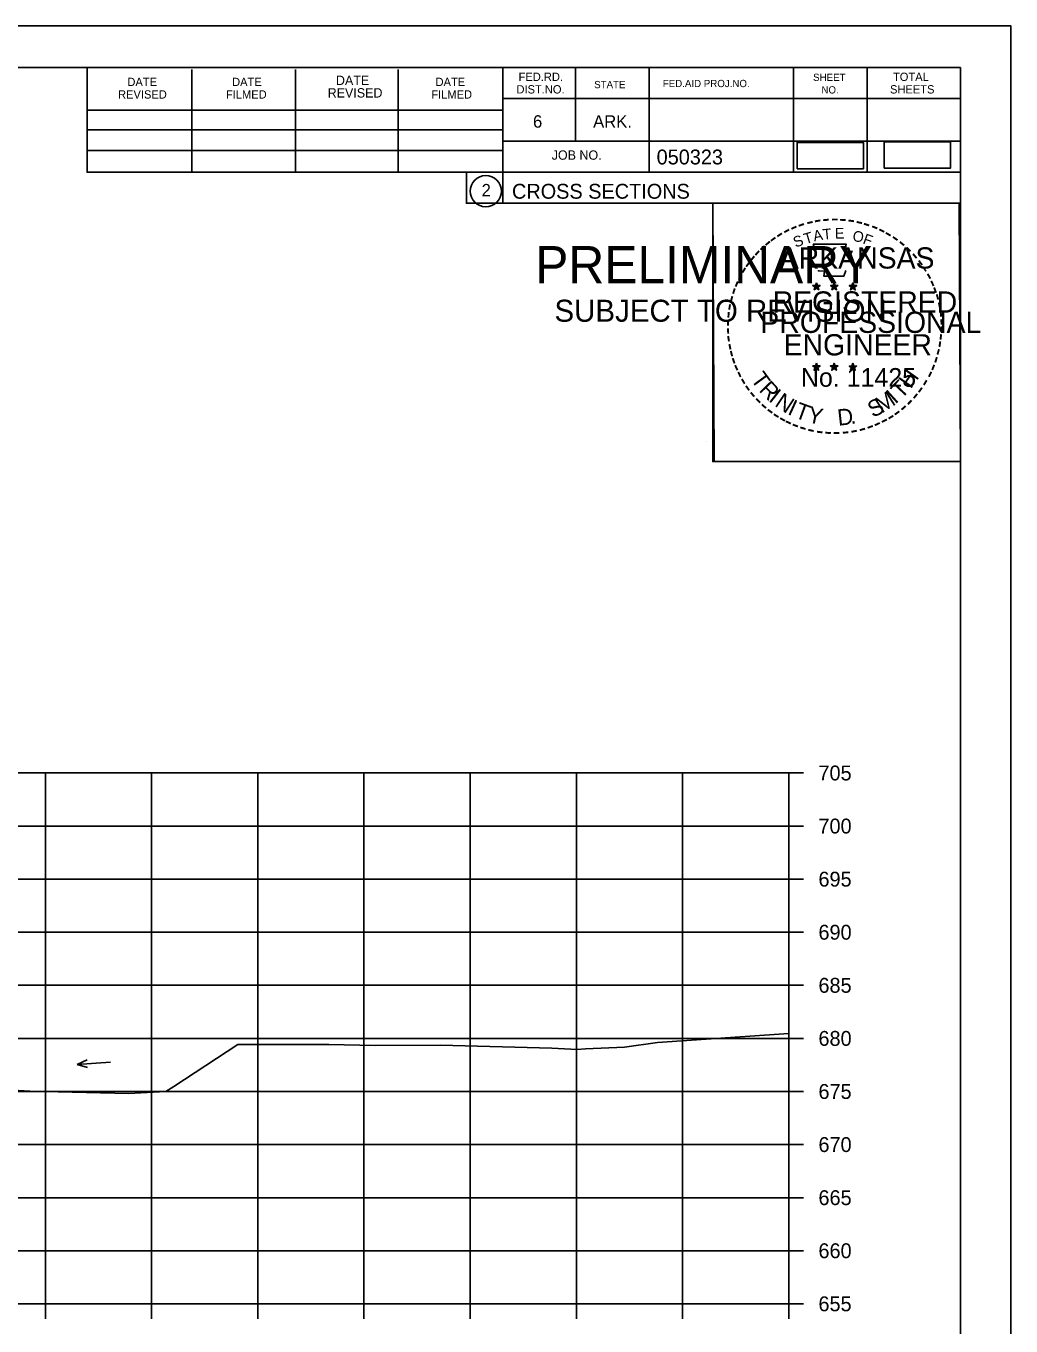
# Model space of a CAD drawing. Extents: x 1360146 to 1361431, y 631444 to 632352.
# Drawn here: x 1360386.9 to 1360479.7, y 631748.4 to 631870.8 of the extents above; entities that cross this region are included whole.
import ezdxf

# ---------------------------------------------------------------- set-up
doc = ezdxf.new("R2010")
doc.units = 0
for name, color, linetype in [('Default', 7, 'Continuous'), ('R_Axis', 7, 'Continuous'), ('R_Axis Annot', 7, 'Continuous'), ('R_Border', 7, 'Continuous'), ('R_Border PE', 7, 'Continuous'), ('R_Border Prem', 7, 'Continuous'), ('R_Exist Surface', 7, 'Continuous'), ('R_Grid', 7, 'Continuous'), ('R_No Plot', 7, 'Continuous'), ('R_Water Annot', 7, 'Continuous')]:
    doc.layers.add(name, color=color, linetype=linetype)

msp = doc.modelspace()

# ---------------------------------------------------------------- linework, layer by layer
at = {"layer": 'Default'}
for points in [[(1360459.55, 631857.39), (1360465.8, 631857.39), (1360465.8, 631859.87), (1360459.55, 631859.87)], [(1360467.76, 631857.46), (1360474.01, 631857.46), (1360474.01, 631859.93), (1360467.76, 631859.93)]]:
    msp.add_lwpolyline(points, close=True, dxfattribs=at)
at = {"layer": 'R_Axis'}
for p, q in [((1360458.77, 631750.48), (1360458.77, 631800.48)), ((1360460.17, 631800.48), (1360458.77, 631800.48)), ((1360460.17, 631795.48), (1360458.77, 631795.48)), ((1360460.17, 631790.48), (1360458.77, 631790.48)), ((1360460.17, 631785.48), (1360458.77, 631785.48)), ((1360460.17, 631780.48), (1360458.77, 631780.48)), ((1360460.17, 631775.48), (1360458.77, 631775.48)), ((1360460.17, 631770.48), (1360458.77, 631770.48)), ((1360460.17, 631765.48), (1360458.77, 631765.48)), ((1360460.17, 631760.48), (1360458.77, 631760.48)), ((1360460.17, 631755.48), (1360458.77, 631755.48)), ((1360178.77, 631750.48), (1360458.77, 631750.48)), ((1360388.77, 631749.08), (1360388.77, 631750.48)), ((1360398.77, 631749.08), (1360398.77, 631750.48)), ((1360408.77, 631749.08), (1360408.77, 631750.48)), ((1360418.77, 631749.08), (1360418.77, 631750.48)), ((1360428.77, 631749.08), (1360428.77, 631750.48)), ((1360438.77, 631749.08), (1360438.77, 631750.48)), ((1360448.77, 631749.08), (1360448.77, 631750.48)), ((1360458.77, 631749.08), (1360458.77, 631750.48)), ((1360460.17, 631750.48), (1360458.77, 631750.48))]:
    msp.add_line(p, q, dxfattribs=at)
at = {"layer": 'R_Border'}
for p, q in [((1360158.77, 631866.94), (1360474.95, 631866.94)), ((1360392.69, 631857.06), (1360392.69, 631866.94)), ((1360402.55, 631857.06), (1360402.55, 631866.74)), ((1360412.31, 631857.06), (1360412.31, 631866.74)), ((1360421.99, 631857.06), (1360421.99, 631866.74)), ((1360431.85, 631866.94), (1360431.85, 631854.14)), ((1360438.69, 631866.94), (1360438.69, 631860)), ((1360445.63, 631866.94), (1360445.63, 631857.06)), ((1360459.21, 631866.94), (1360459.21, 631857.06)), ((1360466.15, 631866.94), (1360466.15, 631857.06)), ((1360474.95, 631661.48), (1360474.95, 631866.94)), ((1360474.95, 631864), (1360431.85, 631864)), ((1360474.95, 631864.02), (1360474.95, 631864.02)), ((1360392.69, 631862.92), (1360431.85, 631862.92)), ((1360392.69, 631861.06), (1360431.85, 631861.06)), ((1360474.95, 631860), (1360431.85, 631860)), ((1360434.81, 631860), (1360474.95, 631860)), ((1360392.69, 631857.06), (1360392.69, 631859.12)), ((1360392.69, 631859.12), (1360431.85, 631859.12)), ((1360474.95, 631857.06), (1360392.69, 631857.06)), ((1360431.85, 631854.14), (1360474.95, 631854.14))]:
    msp.add_line(p, q, dxfattribs=at)
msp.add_circle((1360430.24, 631855.28), 1.47, dxfattribs=at)
at = {"layer": 'R_Border PE'}
for p, q in [((1360461.38, 631846.65), (1360461.34, 631846.4)), ((1360461.38, 631846.29), (1360461.38, 631846.65)), ((1360461.38, 631846.65), (1360461.43, 631846.4)), ((1360463.05, 631846.65), (1360463.01, 631846.4)), ((1360463.05, 631846.29), (1360463.05, 631846.65)), ((1360463.05, 631846.65), (1360463.1, 631846.4)), ((1360464.82, 631846.64), (1360464.78, 631846.39)), ((1360464.82, 631846.27), (1360464.82, 631846.64)), ((1360464.82, 631846.64), (1360464.87, 631846.39)), ((1360461.04, 631846.4), (1360461.38, 631846.29)), ((1360461.04, 631846.4), (1360461.29, 631846.35)), ((1360461.04, 631846.4), (1360461.27, 631846.28)), ((1360461.17, 631845.99), (1360461.38, 631846.29)), ((1360461.17, 631845.99), (1360461.29, 631846.23)), ((1360461.17, 631845.99), (1360461.38, 631846.21)), ((1360461.73, 631846.4), (1360461.38, 631846.29)), ((1360461.6, 631845.99), (1360461.38, 631846.29)), ((1360461.6, 631845.99), (1360461.38, 631846.2)), ((1360461.73, 631846.4), (1360461.45, 631846.35)), ((1360461.6, 631845.99), (1360461.46, 631846.28)), ((1360461.73, 631846.4), (1360461.53, 631846.3)), ((1360462.71, 631846.4), (1360463.05, 631846.29)), ((1360462.71, 631846.4), (1360462.96, 631846.35)), ((1360462.71, 631846.4), (1360462.94, 631846.28)), ((1360462.84, 631845.99), (1360463.05, 631846.29)), ((1360462.84, 631845.99), (1360462.96, 631846.23)), ((1360462.84, 631845.99), (1360463.05, 631846.21)), ((1360463.4, 631846.4), (1360463.05, 631846.29)), ((1360463.27, 631845.99), (1360463.05, 631846.29)), ((1360463.27, 631845.99), (1360463.05, 631846.2)), ((1360463.4, 631846.4), (1360463.12, 631846.35)), ((1360463.27, 631845.99), (1360463.13, 631846.28)), ((1360463.4, 631846.4), (1360463.2, 631846.3)), ((1360464.47, 631846.39), (1360464.82, 631846.27)), ((1360464.47, 631846.39), (1360464.72, 631846.34)), ((1360464.47, 631846.39), (1360464.71, 631846.26)), ((1360464.6, 631845.98), (1360464.82, 631846.27)), ((1360464.6, 631845.98), (1360464.73, 631846.22)), ((1360464.6, 631845.98), (1360464.82, 631846.19)), ((1360465.17, 631846.39), (1360464.82, 631846.27)), ((1360465.03, 631845.98), (1360464.82, 631846.27)), ((1360465.03, 631845.98), (1360464.82, 631846.19)), ((1360465.17, 631846.39), (1360464.88, 631846.34)), ((1360465.03, 631845.98), (1360464.89, 631846.27)), ((1360465.17, 631846.39), (1360464.96, 631846.28)), ((1360461.03, 631838.82), (1360461.38, 631838.71)), ((1360461.03, 631838.82), (1360461.28, 631838.78)), ((1360461.03, 631838.82), (1360461.27, 631838.7)), ((1360461.16, 631838.42), (1360461.38, 631838.71)), ((1360461.16, 631838.42), (1360461.29, 631838.66)), ((1360461.16, 631838.42), (1360461.38, 631838.63)), ((1360461.38, 631839.08), (1360461.34, 631838.83)), ((1360461.38, 631838.71), (1360461.38, 631839.08)), ((1360461.38, 631839.08), (1360461.43, 631838.83)), ((1360461.73, 631838.82), (1360461.38, 631838.71)), ((1360461.59, 631838.42), (1360461.38, 631838.71)), ((1360461.59, 631838.42), (1360461.38, 631838.63)), ((1360461.73, 631838.82), (1360461.44, 631838.78)), ((1360461.59, 631838.42), (1360461.46, 631838.71)), ((1360461.73, 631838.82), (1360461.52, 631838.72)), ((1360462.7, 631838.82), (1360463.05, 631838.71)), ((1360462.7, 631838.82), (1360462.95, 631838.78)), ((1360462.7, 631838.82), (1360462.94, 631838.7)), ((1360462.83, 631838.42), (1360463.05, 631838.71)), ((1360462.83, 631838.42), (1360462.96, 631838.66)), ((1360462.83, 631838.42), (1360463.05, 631838.63)), ((1360463.05, 631839.08), (1360463.01, 631838.83)), ((1360463.05, 631838.71), (1360463.05, 631839.08)), ((1360463.05, 631839.08), (1360463.1, 631838.83)), ((1360463.4, 631838.82), (1360463.05, 631838.71)), ((1360463.26, 631838.42), (1360463.05, 631838.71)), ((1360463.26, 631838.42), (1360463.05, 631838.63)), ((1360463.4, 631838.82), (1360463.11, 631838.78)), ((1360463.26, 631838.42), (1360463.13, 631838.71)), ((1360463.4, 631838.82), (1360463.19, 631838.72)), ((1360464.47, 631838.81), (1360464.82, 631838.7)), ((1360464.47, 631838.81), (1360464.72, 631838.77)), ((1360464.47, 631838.81), (1360464.7, 631838.69)), ((1360464.6, 631838.41), (1360464.82, 631838.7)), ((1360464.6, 631838.41), (1360464.73, 631838.65)), ((1360464.6, 631838.41), (1360464.81, 631838.62)), ((1360464.82, 631839.07), (1360464.78, 631838.82)), ((1360465.03, 631838.41), (1360464.81, 631838.62)), ((1360464.82, 631838.7), (1360464.82, 631839.07)), ((1360464.82, 631839.07), (1360464.87, 631838.82)), ((1360465.16, 631838.81), (1360464.82, 631838.7)), ((1360465.03, 631838.41), (1360464.82, 631838.7)), ((1360465.16, 631838.81), (1360464.88, 631838.77)), ((1360465.03, 631838.41), (1360464.89, 631838.7)), ((1360465.16, 631838.81), (1360464.96, 631838.71))]:
    msp.add_line(p, q, dxfattribs=at)
for points in [[(1360461.08, 631850.28), (1360461.35, 631849.45)], [(1360464.59, 631849.35), (1360464.73, 631849.64), (1360464.04, 631849.61), (1360464.19, 631850.28), (1360461.08, 631850.28)], [(1360461.57, 631847.85), (1360461.57, 631847.77), (1360462.13, 631847.75), (1360462.08, 631847.27), (1360463.95, 631847.27), (1360464.15, 631847.81)], [(1360461.38, 631846.65), (1360461.6, 631845.99), (1360461.04, 631846.4), (1360461.73, 631846.4), (1360461.17, 631845.99), (1360461.38, 631846.65)], [(1360463.05, 631846.65), (1360463.27, 631845.99), (1360462.71, 631846.4), (1360463.4, 631846.4), (1360462.84, 631845.99), (1360463.05, 631846.65)], [(1360464.82, 631846.64), (1360465.03, 631845.98), (1360464.47, 631846.39), (1360465.17, 631846.39), (1360464.6, 631845.98), (1360464.82, 631846.64)], [(1360461.38, 631839.08), (1360461.59, 631838.42), (1360461.03, 631838.82), (1360461.73, 631838.82), (1360461.16, 631838.42), (1360461.38, 631839.08)], [(1360463.05, 631839.08), (1360463.26, 631838.42), (1360462.7, 631838.82), (1360463.4, 631838.82), (1360462.83, 631838.42), (1360463.05, 631839.08)], [(1360464.82, 631839.07), (1360465.03, 631838.41), (1360464.47, 631838.81), (1360465.16, 631838.81), (1360464.6, 631838.41), (1360464.82, 631839.07)]]:
    msp.add_lwpolyline(points, dxfattribs=at)
for centre, radius in [((1360461.38, 631846.29), 0.172), ((1360461.38, 631846.29), 0.145), ((1360461.38, 631846.29), 0.116), ((1360461.38, 631846.29), 0.0991), ((1360461.38, 631846.29), 0.0747), ((1360461.38, 631846.29), 0.0495), ((1360461.38, 631846.29), 0.0296), ((1360463.05, 631846.29), 0.172), ((1360463.05, 631846.29), 0.145), ((1360463.05, 631846.29), 0.116), ((1360463.05, 631846.29), 0.0991), ((1360463.05, 631846.29), 0.0747), ((1360463.05, 631846.29), 0.0495), ((1360463.05, 631846.29), 0.0296), ((1360464.82, 631846.27), 0.172), ((1360464.82, 631846.27), 0.145), ((1360464.82, 631846.27), 0.116), ((1360464.82, 631846.27), 0.0991), ((1360464.82, 631846.27), 0.0747), ((1360464.82, 631846.27), 0.0495), ((1360464.82, 631846.27), 0.0296), ((1360461.38, 631838.71), 0.172), ((1360461.38, 631838.71), 0.145), ((1360461.38, 631838.71), 0.116), ((1360461.38, 631838.71), 0.0991), ((1360461.38, 631838.71), 0.0747), ((1360461.38, 631838.71), 0.0495), ((1360461.38, 631838.71), 0.0296), ((1360463.05, 631838.71), 0.172), ((1360463.05, 631838.71), 0.145), ((1360463.05, 631838.71), 0.116), ((1360463.05, 631838.71), 0.0991), ((1360463.05, 631838.71), 0.0747), ((1360463.05, 631838.71), 0.0495), ((1360463.05, 631838.71), 0.0296), ((1360464.82, 631838.7), 0.172), ((1360464.82, 631838.7), 0.145), ((1360464.82, 631838.7), 0.116), ((1360464.82, 631838.7), 0.0991), ((1360464.82, 631838.7), 0.0747), ((1360464.82, 631838.7), 0.0495), ((1360464.82, 631838.7), 0.0296)]:
    msp.add_circle(centre, radius, dxfattribs=at)
at = {"layer": 'R_Exist Surface'}
msp.add_lwpolyline([(1360381.41, 631770.85), (1360387.29, 631770.51), (1360396.64, 631770.29), (1360398.92, 631770.41), (1360400.1, 631770.49), (1360400.86, 631770.96), (1360406.9, 631774.92), (1360415.45, 631774.91), (1360419.82, 631774.82), (1360425.98, 631774.85), (1360436.47, 631774.56), (1360438.84, 631774.43), (1360439.62, 631774.49), (1360443.29, 631774.64), (1360446.42, 631775.1), (1360458.77, 631775.95)], dxfattribs=at)
at = {"layer": 'R_Grid'}
for p, q in [((1360178.77, 631800.48), (1360458.77, 631800.48)), ((1360388.77, 631750.48), (1360388.77, 631800.48)), ((1360398.77, 631750.48), (1360398.77, 631800.48)), ((1360408.77, 631750.48), (1360408.77, 631800.48)), ((1360418.77, 631750.48), (1360418.77, 631800.48)), ((1360428.77, 631750.48), (1360428.77, 631800.48)), ((1360438.77, 631750.48), (1360438.77, 631800.48)), ((1360448.77, 631750.48), (1360448.77, 631800.48)), ((1360458.77, 631750.48), (1360458.77, 631800.48)), ((1360178.77, 631795.48), (1360458.77, 631795.48)), ((1360178.77, 631790.48), (1360458.77, 631790.48)), ((1360178.77, 631785.48), (1360458.77, 631785.48)), ((1360178.77, 631780.48), (1360458.77, 631780.48)), ((1360178.77, 631775.48), (1360458.77, 631775.48)), ((1360178.77, 631770.48), (1360458.77, 631770.48)), ((1360178.77, 631765.48), (1360458.77, 631765.48)), ((1360178.77, 631760.48), (1360458.77, 631760.48)), ((1360178.77, 631755.48), (1360458.77, 631755.48)), ((1360178.77, 631750.48), (1360458.77, 631750.48))]:
    msp.add_line(p, q, dxfattribs=at)
at = {"layer": 'R_No Plot'}
for p, q in [((1360146.37, 631870.84), (1360479.7, 631870.84)), ((1360450.99, 631831.69), (1360450.99, 631831.69))]:
    msp.add_line(p, q, dxfattribs=at)
for points in [[(1360146.36, 631870.84), (1360479.7, 631870.84), (1360479.7, 631657.5), (1360146.36, 631657.5)], [(1360392.69, 631866.94), (1360392.69, 631857.06), (1360428.42, 631857.06), (1360428.42, 631854.14), (1360451.62, 631854.14), (1360451.62, 631829.81), (1360474.95, 631829.81), (1360474.95, 631661.48), (1360158.77, 631661.48), (1360158.77, 631866.94)], [(1360451.62, 631854.14), (1360474.83, 631854.14), (1360474.95, 631829.81), (1360451.74, 631829.81)]]:
    msp.add_lwpolyline(points, close=True, dxfattribs=at)
at = {"layer": 'R_Water Annot'}
for p, q in [((1360391.76, 631773.03), (1360392.69, 631773.45)), ((1360394.89, 631773.25), (1360391.76, 631773.03)), ((1360391.76, 631773.03), (1360392.74, 631772.75))]:
    msp.add_line(p, q, dxfattribs=at)

# ---------------------------------------------------------------- texts
at = {"layer": 'R_Axis Annot'}
for s, p in [('705', (1360461.57, 631799.78)), ('700', (1360461.57, 631794.78)), ('695', (1360461.57, 631789.78)), ('690', (1360461.57, 631784.78)), ('685', (1360461.57, 631779.78)), ('680', (1360461.57, 631774.78)), ('675', (1360461.57, 631769.78)), ('670', (1360461.57, 631764.78)), ('665', (1360461.57, 631759.78)), ('660', (1360461.57, 631754.78)), ('655', (1360461.57, 631749.78))]:
    msp.add_text(s, height=1.4, dxfattribs=at).set_placement(p)
at = {"layer": 'R_Border'}
for s, height, p in [('DATE', 0.879, (1360416.13, 631865.28)), ('FED.RD.', 0.782, (1360433.33, 631865.66)), ('SHEET', 0.684, (1360461.07, 631865.66)), ('TOTAL', 0.782, (1360468.59, 631865.66)), ('DATE', 0.782, (1360396.49, 631865.18)), ('DATE', 0.782, (1360406.35, 631865.18)), ('REVISED', 0.879, (1360415.35, 631864.1)), ('DATE', 0.782, (1360425.51, 631865.18)), ('DIST.NO.', 0.782, (1360433.13, 631864.48)), ('STATE', 0.684, (1360440.45, 631864.98)), ('FED.AID PROJ.NO.', 0.684, (1360446.91, 631865.08)), ('NO.', 0.684, (1360461.85, 631864.48)), ('SHEETS', 0.782, (1360468.31, 631864.48)), ('REVISED', 0.782, (1360395.61, 631864)), ('FILMED', 0.782, (1360405.77, 631864)), ('FILMED', 0.782, (1360425.11, 631864)), ('6', 1.17, (1360434.69, 631861.26)), ('ARK.', 1.172, (1360440.35, 631861.26)), ('JOB NO.', 0.879, (1360436.45, 631858.24)), ('050323', 1.4, (1360446.33, 631857.8)), ('2', 1.17, (1360429.85, 631854.79)), ('CROSS SECTIONS', 1.4, (1360432.71, 631854.57))]:
    msp.add_text(s, height=height, rotation=360, dxfattribs=at).set_placement(p)
at = {"layer": 'R_Border PE'}
for s, height, rotation, p in [('-', 1.6, 5.8968, (1360461.98, 631851.92)), ('-', 1.6, 0.1862, (1360462.75, 631851.99)), ('-', 1.6, 357.743, (1360463.48, 631851.97)), ('-', 1.6, 28.7918, (1360458.56, 631850.82)), ('-', 1.6, 24.3072, (1360459.19, 631851.13)), ('-', 1.6, 19.1761, (1360459.82, 631851.4)), ('T', 1, 16.4036, (1360460.35, 631850.28)), ('-', 1.6, 13.6301, (1360460.57, 631851.64)), ('A', 1, 11.2132, (1360461.17, 631850.54)), ('-', 1.6, 10.2193, (1360461.25, 631851.81)), ('T', 1, 6.0228, (1360462.02, 631850.7)), ('E', 1, 0.8323, (1360463.13, 631850.81)), ('-', 1.6, 352.1617, (1360464.22, 631851.92)), ('O', 1, 350.4515, (1360464.73, 631850.6)), ('-', 1.6, 347.2049, (1360464.94, 631851.8)), ('-', 1.6, 342.3362, (1360465.57, 631851.65)), ('-', 1.6, 337.8551, (1360466.31, 631851.43)), ('-', 1.6, 334.1211, (1360466.94, 631851.16)), ('-', 1.6, 329.6409, (1360467.52, 631850.87)), ('-', 1.6, 42.9622, (1360456.47, 631849.26)), ('-', 1.6, 38.9507, (1360456.91, 631849.67)), ('-', 1.6, 36.2317, (1360457.38, 631850.05)), ('-', 1.6, 34.0636, (1360457.96, 631850.45)), ('S', 1, 21.594, (1360459.43, 631849.95)), ('F', 1, 340.0707, (1360465.68, 631850.37)), ('-', 1.6, 325.8627, (1360468.16, 631850.51)), ('-', 1.6, 320.5297, (1360468.77, 631850.09)), ('-', 1.6, 50.6142, (1360455.62, 631848.29)), ('-', 1.6, 48.423, (1360456.03, 631848.78)), ('ARKANSAS', 2, 360, (1360457.93, 631847.99)), ('-', 1.6, 315.5786, (1360469.37, 631849.6)), ('-', 1.6, 309.8797, (1360469.94, 631849.05)), ('-', 1.6, 58.0706, (1360454.88, 631847.2)), ('-', 1.6, 54.2325, (1360455.21, 631847.73)), ('-', 1.6, 306.6522, (1360470.47, 631848.45)), ('-', 1.4, 303.6753, (1360470.95, 631847.88)), ('-', 1.6, 67.7743, (1360454.31, 631845.97)), ('-', 1.6, 62.8713, (1360454.57, 631846.58)), ('-', 1.6, 299.6684, (1360471.27, 631847.27)), ('-', 1.6, 294.6628, (1360471.59, 631846.66)), ('-', 1.6, 75.461, (1360453.9, 631844.63)), ('-', 1.6, 72.3945, (1360454.09, 631845.34)), ('REGISTERED', 2, 360, (1360457.25, 631843.84)), ('DWB', 0.01, 360, (1360461.37, 631846.28)), ('DWB', 0.01, 360, (1360463.04, 631846.28)), ('DWB', 0.01, 360, (1360464.81, 631846.27)), ('-', 1.6, 290.5728, (1360471.85, 631846.08)), ('-', 1.6, 285.1233, (1360472.09, 631845.5)), ('-', 1.6, 81.2013, (1360453.76, 631843.92)), ('-', 1.6, 280.5493, (1360472.29, 631844.76)), ('-', 1.6, 89.0622, (1360453.66, 631842.52)), ('-', 1.6, 85.1863, (1360453.69, 631843.23)), ('PROFESSIONAL', 2, 360, (1360456.1, 631841.93)), ('-', 1.6, 276.5962, (1360472.45, 631843.99)), ('-', 1.6, 274.3301, (1360472.51, 631843.27)), ('-', 1.6, 94.1959, (1360453.7, 631841.8)), ('-', 1.6, 98.9479, (1360453.77, 631841.13)), ('ENGINEER', 2, 360, (1360458.29, 631839.81)), ('-', 1.6, 263.5172, (1360472.52, 631841.97)), ('-', 1.6, 269.9407, (1360472.54, 631842.64)), ('-', 1.6, 101.7149, (1360453.91, 631840.4)), ('-', 1.6, 255.7626, (1360472.34, 631840.64)), ('-', 1.6, 260.9953, (1360472.45, 631841.32)), ('-', 1.6, 105.4578, (1360454.07, 631839.8)), ('-', 1.6, 109.0874, (1360454.28, 631839.17)), ('-', 1.6, 252.8681, (1360472.16, 631839.92)), ('-', 1.6, 114.0643, (1360454.54, 631838.58)), ('-', 1.6, 115.7289, (1360454.84, 631837.96)), ('T', 1.54, 306.0406, (1360455.14, 631837.55)), ('No. 11425', 1.757, 360, (1360459.92, 631836.86)), ('DWB', 0.01, 360, (1360461.37, 631838.71)), ('DWB', 0.01, 360, (1360463.04, 631838.71)), ('DWB', 0.01, 360, (1360464.8, 631838.7)), ('H', 1.54, 54.6088, (1360470.26, 631836.59)), ('-', 1.6, 244.6197, (1360471.68, 631838.62)), ('-', 1.6, 247.8887, (1360471.94, 631839.25)), ('-', 1.6, 120.4471, (1360455.2, 631837.37)), ('-', 1.6, 125.8934, (1360455.6, 631836.81)), ('R', 1.54, 314.005, (1360455.9, 631836.5)), ('T', 1.54, 46.6444, (1360469.37, 631835.64)), ('-', 1.6, 233.8452, (1360470.88, 631837.21)), ('-', 1.6, 239.0712, (1360471.28, 631837.87)), ('-', 1.6, 130.7181, (1360456.06, 631836.26)), ('-', 1.6, 134.2238, (1360456.58, 631835.72)), ('I', 1.54, 321.9694, (1360456.8, 631835.57)), ('N', 1.54, 326.5002, (1360457.37, 631835.1)), ('I', 1.54, 335.3603, (1360458.58, 631834.31)), ('S', 1.54, 26.9312, (1360466.69, 631833.91)), ('M', 1.54, 32.6563, (1360467.52, 631834.32)), ('I', 1.54, 42.1136, (1360468.81, 631835.17)), ('-', 1.6, 225.7653, (1360469.97, 631836.08)), ('-', 1.6, 231.2538, (1360470.45, 631836.65)), ('-', 1.6, 138.9338, (1360457.11, 631835.25)), ('-', 1.6, 144.6463, (1360457.66, 631834.85)), ('-', 1.6, 148.0898, (1360458.22, 631834.47)), ('T', 1.54, 339.8912, (1360459.24, 631833.99)), ('Y', 1.54, 347.8556, (1360460.46, 631833.54)), ('D', 1.54, 6.3969, (1360463.44, 631833.18)), ('-', 1.6, 215.7363, (1360468.9, 631835.1)), ('-', 1.6, 221.0851, (1360469.45, 631835.57)), ('-', 1.6, 151.5704, (1360458.8, 631834.15)), ('-', 1.6, 154.6002, (1360459.32, 631833.9)), ('-', 1.6, 158.5612, (1360459.95, 631833.65)), ('-', 1.6, 162.7983, (1360460.63, 631833.44)), ('.', 1.54, 13.7642, (1360464.63, 631833.31)), ('-', 1.6, 200.7184, (1360466.56, 631833.78)), ('-', 1.6, 204.2516, (1360467.18, 631834.05)), ('-', 1.6, 207.3568, (1360467.81, 631834.37)), ('-', 1.6, 212.2491, (1360468.37, 631834.71)), ('-', 1.6, 167.5555, (1360461.35, 631833.27)), ('-', 1.6, 173.1155, (1360462.12, 631833.16)), ('-', 1.6, 176.5183, (1360462.87, 631833.11)), ('-', 1.6, 181.5918, (1360463.61, 631833.13)), ('-', 1.6, 185.8167, (1360464.42, 631833.2)), ('-', 1.6, 191.2858, (1360465.16, 631833.34)), ('-', 1.6, 195.4743, (1360465.89, 631833.53))]:
    msp.add_text(s, height=height, rotation=rotation, dxfattribs=at).set_placement(p)
at = {"layer": 'R_Border Prem'}
for s, height, p in [('PRELIMINARY', 3.5, (1360434.9, 631846.61)), ('DWB', 0.01, (1360435.65, 631848.45)), ('SUBJECT TO REVISION', 2.0751, (1360436.71, 631842.98))]:
    msp.add_text(s, height=height, rotation=360, dxfattribs=at).set_placement(p)

doc.saveas('drawing.dxf')
